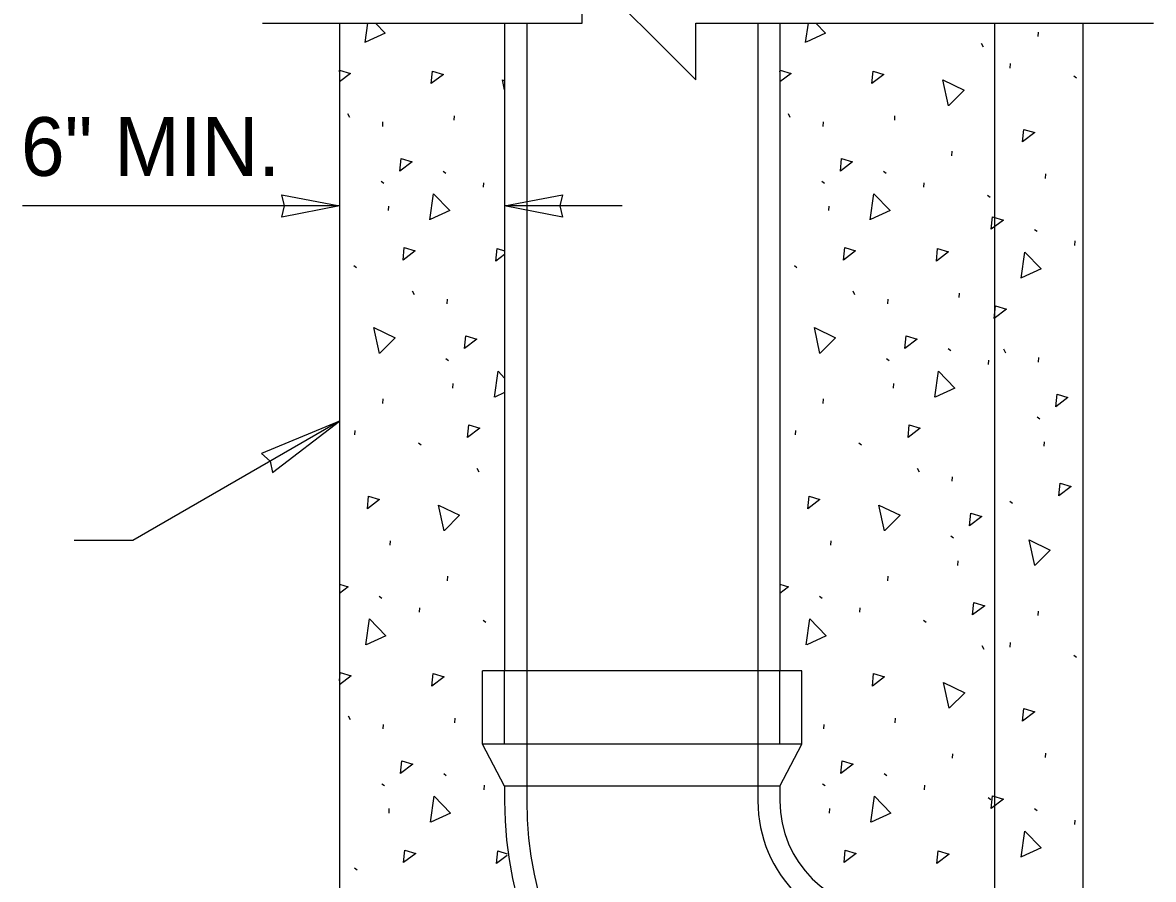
# Model space of a CAD drawing. Extents: x 99862 to 103151, y 100000 to 102076.
# Drawn here: x 101882.3 to 102190.4, y 100763.6 to 100997.1 of the extents above; entities that cross this region are included whole.
import ezdxf

# ---------------------------------------------------------------- set-up
doc = ezdxf.new("R2010")
doc.units = 0
for name, color, linetype in [('Level 1', 7, 'Continuous'), ('Level 15', 7, 'Continuous'), ('Level 17', 7, 'Continuous'), ('Level 19', 7, 'Continuous'), ('Level 20', 7, 'Continuous'), ('Level 6', 7, 'Continuous')]:
    doc.layers.add(name, color=color, linetype=linetype)

msp = doc.modelspace()

# ---------------------------------------------------------------- linework, layer by layer
at = {"layer": 'Level 1'}
for p, q in [((102013.66, 100996.95), (102013.66, 100820.43)), ((102088.66, 100996.95), (102088.66, 100820.43)), ((102171.16, 100996.95), (102171.16, 100760.98)), ((102007.66, 100800.43), (102007.66, 100820.43)), ((102094.66, 100820.43), (102007.66, 100820.43)), ((102094.66, 100800.43), (102094.66, 100820.43)), ((102013.66, 100788.98), (102007.66, 100800.43)), ((102094.66, 100800.43), (102007.66, 100800.43)), ((102088.66, 100788.98), (102094.66, 100800.43)), ((102013.66, 100788.98), (102013.66, 100784.98)), ((102088.66, 100788.98), (102013.66, 100788.98)), ((102088.66, 100788.98), (102088.66, 100784.98))]:
    msp.add_line(p, q, dxfattribs=at)
for radius in [105, 30]:
    msp.add_arc((102118.66, 100784.98), radius, 180, 270, dxfattribs=at)
at = {"layer": 'Level 15'}
for p, q in [((101968.66, 100947.12), (101882.33, 100947.12)), ((102045.66, 100947.12), (102013.66, 100947.12)), ((101968.66, 100888.46), (101912.37, 100855.96)), ((101912.37, 100855.96), (101896.37, 100855.96))]:
    msp.add_line(p, q, dxfattribs=at)
msp.add_lwpolyline([(101947.66, 100996.95), (102034.76, 100996.95), (102034.76, 101012.44), (102065.74, 100981.47), (102065.74, 100996.95), (102190.41, 100996.95)], dxfattribs=at)
for points in [[(101968.66, 100947.12), (101952.93, 100944.04), (101953.66, 100947.12), (101952.93, 100950.2)], [(102013.66, 100947.12), (102029.38, 100950.2), (102028.66, 100947.12), (102029.38, 100944.04)], [(101968.66, 100888.46), (101947.4, 100879.63), (101949.8, 100877.57), (101950.38, 100874.46)]]:
    msp.add_lwpolyline(points, close=True, dxfattribs=at)
at = {"layer": 'Level 17'}
for p, q in [((101968.66, 100996.95), (101968.66, 100629.98)), ((102147.16, 100996.95), (102147.16, 100754.98))]:
    msp.add_line(p, q, dxfattribs=at)
at = {"layer": 'Level 19'}
for p, q in [((102158.99, 100993.29), (102159.08, 100994.51)), ((102143.51, 100991.53), (102144.01, 100990.52)), ((102151.4, 100984.72), (102151.48, 100985.94)), ((102168.72, 100982.55), (102169.44, 100982.03)), ((101970.88, 100972.37), (101971.38, 100971.36)), ((101999.93, 100970.5), (102000.01, 100971.72)), ((102090.88, 100972.37), (102091.38, 100971.36)), ((102119.93, 100970.5), (102120.01, 100971.72)), ((101980.43, 100968.82), (101980.51, 100970.04)), ((102100.43, 100968.82), (102100.51, 100970.04)), ((102135.49, 100960.81), (102135.57, 100962.04)), ((101996.88, 100956.63), (101997.6, 100956.1)), ((102116.88, 100956.63), (102117.6, 100956.1)), ((102161.03, 100954.62), (102161.11, 100955.84)), ((101980.06, 100953.88), (101980.78, 100953.35)), ((102007.89, 100952.24), (102007.98, 100953.47)), ((102100.06, 100953.88), (102100.78, 100953.35)), ((102127.89, 100952.24), (102127.98, 100953.47)), ((102145.22, 100950.08), (102145.94, 100949.55)), ((101981.98, 100945.86), (101982.07, 100947.08)), ((102101.98, 100945.86), (102102.07, 100947.08)), ((102157.98, 100940.75), (102158.7, 100940.22)), ((102168.99, 100936.37), (102169.08, 100937.59)), ((101972.59, 100930.93), (101973.31, 100930.4)), ((102092.59, 100930.93), (102093.31, 100930.4)), ((101988.48, 100924.02), (101988.98, 100923.01)), ((101998.02, 100920.47), (101998.11, 100921.69)), ((102108.48, 100924.02), (102108.98, 100923.01)), ((102118.02, 100920.47), (102118.11, 100921.69)), ((102137.52, 100922.15), (102137.61, 100923.37)), ((102134.48, 100908.28), (102135.2, 100907.75)), ((102149.58, 100908.15), (102150.08, 100907.14)), ((101997.66, 100905.53), (101998.38, 100905)), ((102117.66, 100905.53), (102118.38, 100905)), ((102145.49, 100903.9), (102145.57, 100905.12)), ((102159.12, 100904.6), (102159.21, 100905.82)), ((101999.58, 100897.51), (101999.66, 100898.73)), ((102119.58, 100897.51), (102119.66, 100898.73)), ((101980.46, 100893.31), (101980.55, 100894.54)), ((102100.46, 100893.31), (102100.55, 100894.54)), ((102158.76, 100889.65), (102159.48, 100889.12)), ((101972.87, 100884.74), (101972.95, 100885.96)), ((102092.87, 100884.74), (102092.95, 100885.96)), ((101990.19, 100882.58), (101990.91, 100882.05)), ((102110.19, 100882.58), (102110.91, 100882.05)), ((102160.68, 100881.63), (102160.76, 100882.85)), ((102006.08, 100875.67), (102006.58, 100874.66)), ((102126.08, 100875.67), (102126.58, 100874.66)), ((102135.62, 100872.12), (102135.7, 100873.35)), ((102151.29, 100866.7), (102152.01, 100866.17)), ((102135.26, 100857.18), (102135.98, 100856.65)), ((101982.5, 100854.64), (101982.58, 100855.87)), ((102102.5, 100854.64), (102102.58, 100855.87)), ((102137.17, 100849.16), (102137.26, 100850.38)), ((101998.06, 100844.96), (101998.15, 100846.19)), ((102118.06, 100844.96), (102118.15, 100846.19)), ((101979.45, 100840.78), (101980.17, 100840.25)), ((102099.45, 100840.78), (102100.17, 100840.25)), ((101990.46, 100836.39), (101990.55, 100837.62)), ((102110.46, 100836.39), (102110.55, 100837.62)), ((102158.99, 100835.47), (102159.08, 100836.69)), ((102007.79, 100834.23), (102008.51, 100833.7)), ((102127.79, 100834.23), (102128.51, 100833.7)), ((102143.68, 100827.33), (102144.18, 100826.32)), ((102151.4, 100826.89), (102151.48, 100828.12)), ((102168.72, 100824.73), (102169.44, 100824.2)), ((101971.05, 100808.17), (101971.55, 100807.16)), ((102000.1, 100806.3), (102000.18, 100807.52)), ((102120.1, 100806.3), (102120.18, 100807.52)), ((101980.6, 100804.62), (101980.68, 100805.84)), ((102100.6, 100804.62), (102100.68, 100805.84)), ((102135.66, 100796.61), (102135.74, 100797.84)), ((102161.03, 100796.8), (102161.11, 100798.02)), ((101997.05, 100792.43), (101997.77, 100791.9)), ((102117.05, 100792.43), (102117.77, 100791.9)), ((101980.23, 100789.68), (101980.95, 100789.15)), ((102008.06, 100788.04), (102008.15, 100789.27)), ((102100.23, 100789.68), (102100.95, 100789.15)), ((102128.06, 100788.04), (102128.15, 100789.27)), ((102145.39, 100785.88), (102146.11, 100785.35)), ((101982.15, 100781.66), (101982.24, 100782.88)), ((102102.15, 100781.66), (102102.24, 100782.88)), ((102157.98, 100782.93), (102158.7, 100782.4)), ((102168.99, 100778.55), (102169.08, 100779.77)), ((101972.76, 100766.73), (101973.48, 100766.2))]:
    msp.add_line(p, q, dxfattribs=at)
for points in [[(101975.67, 100991.7), (101976.4, 100996.95)], [(101978.45, 100996.95), (101981.11, 100994.21), (101975.79, 100991.75)], [(102095.67, 100991.7), (102096.4, 100996.95)], [(102098.45, 100996.95), (102101.11, 100994.21), (102095.79, 100991.75)], [(101968.66, 100983.66), (101968.7, 100984.14), (101971.68, 100983.24), (101968.66, 100980.93)], [(101993.68, 100980.46), (101994.02, 100983.89), (101996.99, 100982.99), (101993.68, 100980.46)], [(102088.66, 100983.66), (102088.7, 100984.14), (102091.68, 100983.24), (102088.66, 100980.93)], [(102113.68, 100980.46), (102114.02, 100983.89), (102116.99, 100982.99), (102113.68, 100980.46)], [(102013.66, 100978.75), (102013.07, 100981.48), (102013.66, 100981.19)], [(102134.58, 100974.46), (102133.07, 100981.48), (102138.83, 100978.68), (102134.68, 100974.54)], [(102154.78, 100964.58), (102155.12, 100968.01), (102158.09, 100967.11), (102154.78, 100964.58)], [(101985.12, 100956.64), (101985.46, 100960.07), (101988.44, 100959.17), (101985.12, 100956.64)], [(102105.12, 100956.64), (102105.46, 100960.07), (102108.44, 100959.17), (102105.12, 100956.64)], [(101993.27, 100943.35), (101994.25, 100950.46), (101998.71, 100945.86), (101993.38, 100943.4)], [(102113.27, 100943.35), (102114.25, 100950.46), (102118.71, 100945.86), (102113.38, 100943.4)], [(102146.22, 100940.76), (102146.56, 100944.2), (102149.54, 100943.29), (102146.22, 100940.76)], [(101985.97, 100932.36), (101986.3, 100935.79), (101989.28, 100934.89), (101985.97, 100932.36)], [(102011.28, 100932.11), (102011.62, 100935.54), (102013.66, 100934.92)], [(102013.66, 100933.93), (102011.28, 100932.11)], [(102105.97, 100932.36), (102106.3, 100935.79), (102109.28, 100934.89), (102105.97, 100932.36)], [(102131.28, 100932.11), (102131.62, 100935.54), (102134.59, 100934.64), (102131.28, 100932.11)], [(102154.37, 100927.48), (102155.35, 100934.58), (102159.81, 100929.98), (102154.48, 100927.52)], [(102147.07, 100916.48), (102147.4, 100919.91), (102150.38, 100919.01), (102147.07, 100916.48)], [(101979.55, 100906.96), (101978.05, 100913.97), (101983.81, 100911.17), (101979.65, 100907.04)], [(102099.55, 100906.96), (102098.05, 100913.97), (102103.81, 100911.17), (102099.65, 100907.04)], [(102002.72, 100908.29), (102003.06, 100911.72), (102006.04, 100910.82), (102002.72, 100908.29)], [(102122.72, 100908.29), (102123.06, 100911.72), (102126.04, 100910.82), (102122.72, 100908.29)], [(102010.86, 100895), (102011.85, 100902.11), (102013.66, 100900.24)], [(102130.86, 100895), (102131.85, 100902.11), (102136.3, 100897.51), (102130.98, 100895.05)], [(102013.66, 100896.29), (102010.98, 100895.05)], [(102163.82, 100892.42), (102164.16, 100895.85), (102167.14, 100894.95), (102163.82, 100892.42)], [(102003.56, 100884.01), (102003.9, 100887.44), (102006.88, 100886.54), (102003.56, 100884.01)], [(102123.56, 100884.01), (102123.9, 100887.44), (102126.88, 100886.54), (102123.56, 100884.01)], [(102164.67, 100868.13), (102165, 100871.56), (102167.98, 100870.66), (102164.67, 100868.13)], [(101976.25, 100864.61), (101976.59, 100868.04), (101979.56, 100867.14), (101976.25, 100864.61)], [(102096.25, 100864.61), (102096.59, 100868.04), (102099.56, 100867.14), (102096.25, 100864.61)], [(101997.15, 100858.61), (101995.65, 100865.62), (102001.4, 100862.82), (101997.25, 100858.69)], [(102117.15, 100858.61), (102115.65, 100865.62), (102121.4, 100862.82), (102117.25, 100858.69)], [(102140.32, 100859.94), (102140.66, 100863.37), (102143.63, 100862.47), (102140.32, 100859.94)], [(102158.08, 100849.11), (102156.58, 100856.13), (102162.33, 100853.33), (102158.18, 100849.19)], [(101968.66, 100844.03), (101971.01, 100843.32), (101968.66, 100841.53)], [(102088.66, 100844.03), (102091.01, 100843.32), (102088.66, 100841.53)], [(102141.16, 100835.66), (102141.5, 100839.09), (102144.47, 100838.19), (102141.16, 100835.66)], [(101975.84, 100827.5), (101976.83, 100834.6), (101981.28, 100830.01), (101975.96, 100827.55)], [(102095.84, 100827.5), (102096.83, 100834.6), (102101.28, 100830.01), (102095.96, 100827.55)], [(101968.66, 100817.72), (101968.88, 100819.94), (101971.85, 100819.04), (101968.66, 100816.6)], [(101993.85, 100816.26), (101994.19, 100819.69), (101997.16, 100818.79), (101993.85, 100816.26)], [(102113.85, 100816.26), (102114.19, 100819.69), (102117.16, 100818.79), (102113.85, 100816.26)], [(102134.75, 100810.26), (102133.25, 100817.28), (102139, 100814.48), (102134.85, 100810.34)], [(102154.78, 100806.76), (102155.12, 100810.19), (102158.09, 100809.29), (102154.78, 100806.76)], [(101985.29, 100792.44), (101985.63, 100795.87), (101988.61, 100794.97), (101985.29, 100792.44)], [(102105.29, 100792.44), (102105.63, 100795.87), (102108.61, 100794.97), (102105.29, 100792.44)], [(101993.44, 100779.15), (101994.42, 100786.26), (101998.88, 100781.66), (101993.55, 100779.2)], [(102113.44, 100779.15), (102114.42, 100786.26), (102118.88, 100781.66), (102113.55, 100779.2)], [(102146.22, 100782.94), (102146.56, 100786.37), (102149.54, 100785.47), (102146.22, 100782.94)], [(102154.37, 100769.66), (102155.35, 100776.76), (102159.81, 100772.16), (102154.48, 100769.7)], [(101986.14, 100768.16), (101986.47, 100771.59), (101989.45, 100770.69), (101986.14, 100768.16)], [(102011.45, 100767.91), (102011.79, 100771.34), (102014.3, 100770.58)], [(102106.14, 100768.16), (102106.47, 100771.59), (102109.45, 100770.69), (102106.14, 100768.16)], [(102131.45, 100767.91), (102131.79, 100771.34), (102134.76, 100770.44), (102131.45, 100767.91)], [(102014.32, 100770.1), (102011.45, 100767.91)]]:
    msp.add_lwpolyline(points, dxfattribs=at)
at = {"layer": 'Level 6'}
for p, q in [((102019.66, 100996.95), (102019.66, 100784.98)), ((102082.66, 100996.95), (102082.66, 100784.98)), ((102013.66, 100800.43), (102013.66, 100820.43)), ((102088.66, 100800.43), (102088.66, 100820.43))]:
    msp.add_line(p, q, dxfattribs=at)
for radius in [99, 36]:
    msp.add_arc((102118.66, 100784.98), radius, 180, 270, dxfattribs=at)

# ---------------------------------------------------------------- texts
at = {"layer": 'Level 20'}
msp.add_text('6" MIN.', height=16, rotation=360, dxfattribs=at).set_placement((101881.88, 100955.33))

doc.saveas('drawing.dxf')
